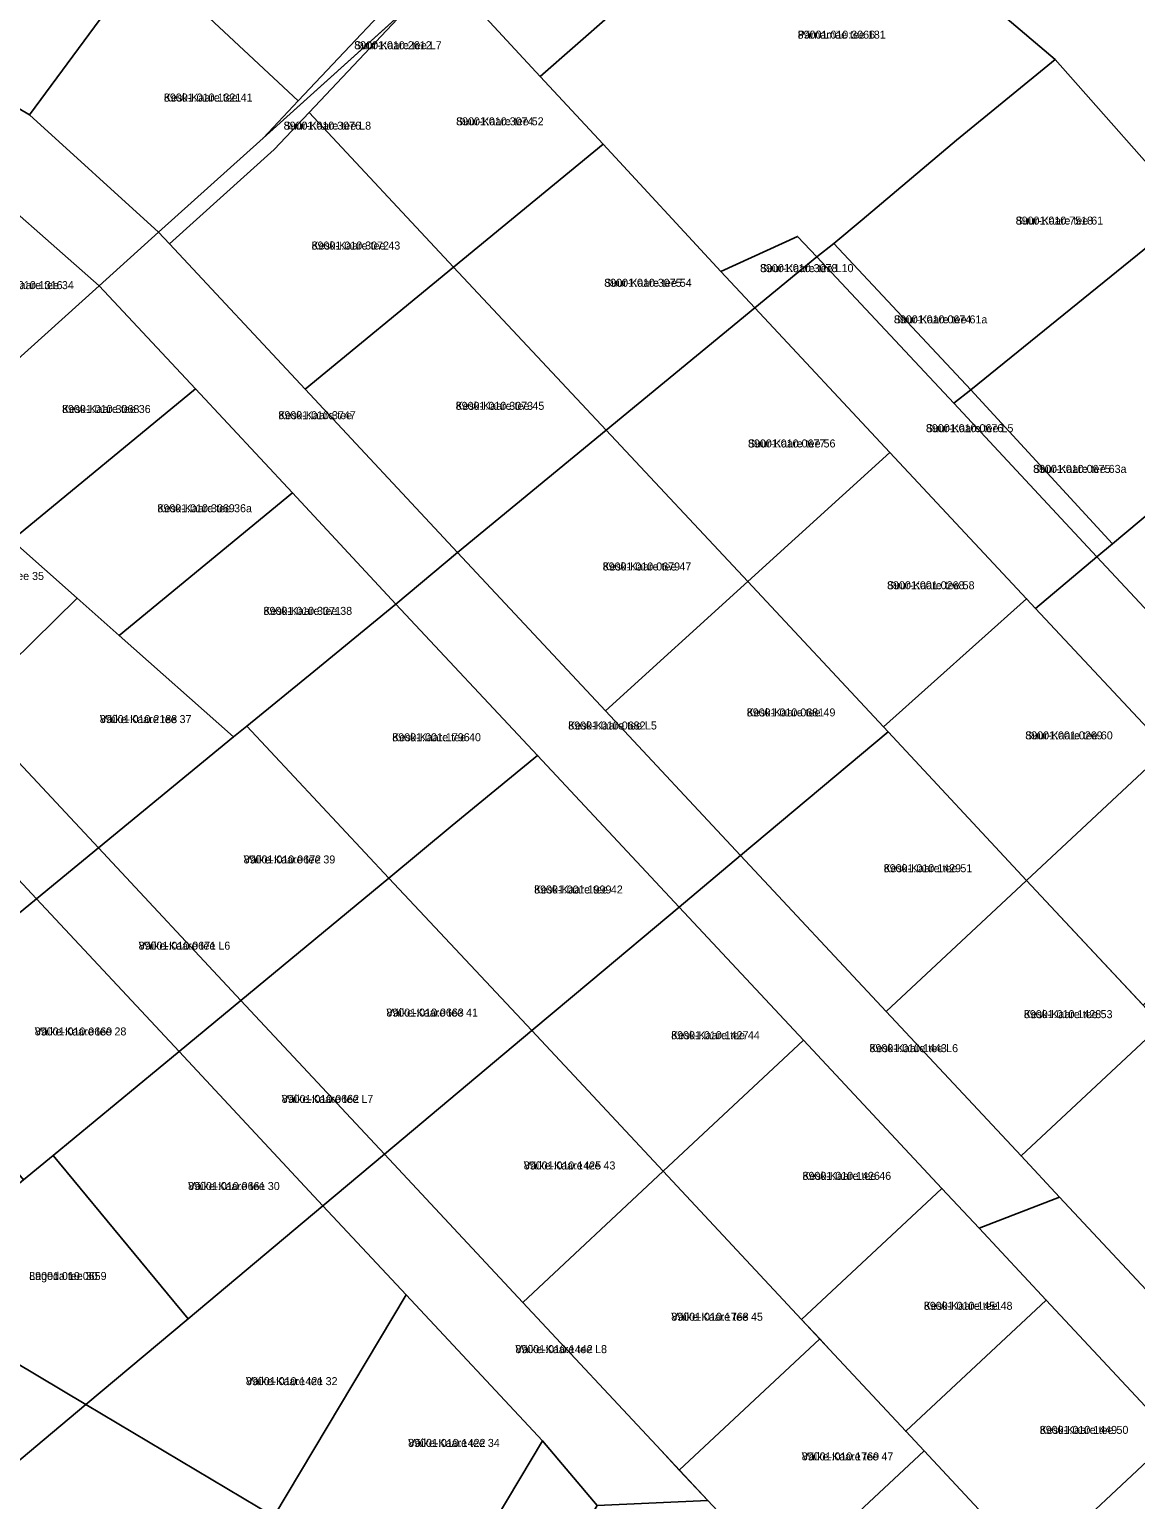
# Model space of a CAD drawing. Extents: x 526849 to 562296, y 6591741 to 6618546.
# Drawn here: x 548539.4 to 548746.7, y 6596665.2 to 6596940.7 of the extents above; entities that cross this region are included whole.
import ezdxf

# ---------------------------------------------------------------- set-up
doc = ezdxf.new("R2010")
doc.units = 0
for name, color, linetype in [('L_AADRESS', 7, 'Continuous'), ('PIIR', 7, 'Continuous'), ('TUNNUS', 7, 'Continuous')]:
    doc.layers.add(name, color=color, linetype=linetype)

msp = doc.modelspace()

# ---------------------------------------------------------------- linework, layer by layer
at = {"layer": 'PIIR'}
for points in [[(548635.14, 6596931.86), (548674.5, 6596966.36), (548653.8, 6596983.92), (548663.62, 6596992.77), (548731.64, 6596935.04), (548713.16, 6596919.89), (548695.51, 6596905.01), (548690.14, 6596900.55), (548687.01, 6596898.06), (548683.37, 6596901.89), (548669.02, 6596895.33), (548646.93, 6596919.15)], [(548624.14, 6596943.73), (548635.1, 6596953.6), (548629.61, 6596959.48), (548646.06, 6596976.95), (548653.8, 6596983.92), (548674.5, 6596966.36), (548635.14, 6596931.86)], [(548564.76, 6596950.65), (548586.85, 6596979.08), (548614.58, 6596953.6), (548589.77, 6596927.27)], [(548527.03, 6596973.58), (548538.19, 6596968), (548560.79, 6596953.66), (548539.44, 6596924.68), (548511.98, 6596940.88)], [(548299.97, 6596894.58), (548328.12, 6596911), (548358.36, 6596928.64), (548387.76, 6596943.88), (548418.39, 6596952.73), (548450.18, 6596955.2), (548481.81, 6596951.2), (548511.98, 6596940.88), (548539.44, 6596924.68), (548563.62, 6596902.65), (548552.48, 6596892.61), (548526.47, 6596915.49), (548491.86, 6596932.76), (548446.84, 6596940.25), (548405.11, 6596934.11), (548367.93, 6596916.86), (548336.83, 6596898.72), (548314.44, 6596885.66)], [(548560.79, 6596953.66), (548564.76, 6596950.65), (548589.77, 6596927.27), (548583.2, 6596920.29), (548563.62, 6596902.65), (548539.44, 6596924.68)], [(548614.58, 6596953.6), (548617.34, 6596951.06), (548583.2, 6596920.29), (548589.77, 6596927.27)], [(548591.83, 6596925.07), (548610.49, 6596944.89), (548617.34, 6596951.06), (548624.14, 6596943.73), (548635.14, 6596931.86), (548646.93, 6596919.15), (548618.91, 6596896.13)], [(548563.62, 6596902.65), (548583.2, 6596920.29), (548610.49, 6596944.89), (548591.83, 6596925.07), (548585.3, 6596918.14), (548565.67, 6596900.46)], [(548713.16, 6596919.89), (548731.64, 6596935.04), (548756.96, 6596906.42), (548715.84, 6596873.15), (548690.14, 6596900.55), (548695.51, 6596905.01)], [(548565.67, 6596900.46), (548585.3, 6596918.14), (548591.83, 6596925.07), (548618.91, 6596896.13), (548591.07, 6596873.26)], [(548618.91, 6596896.13), (548646.93, 6596919.15), (548669.02, 6596895.33), (548675.38, 6596888.47), (548647.51, 6596865.57)], [(548526.47, 6596915.49), (548552.48, 6596892.61), (548525.69, 6596868.52), (548506.15, 6596885.77)], [(548782.29, 6596877.71), (548742.41, 6596844.29), (548715.84, 6596873.15), (548756.96, 6596906.42)], [(548608.06, 6596832.97), (548588.71, 6596853.81), (548570.52, 6596873.29), (548552.48, 6596892.61), (548563.62, 6596902.65), (548565.67, 6596900.46), (548591.07, 6596873.26), (548619.65, 6596842.66)], [(548669.02, 6596895.33), (548683.37, 6596901.89), (548687.01, 6596898.06), (548675.38, 6596888.47)], [(548687.01, 6596898.06), (548690.14, 6596900.55), (548715.84, 6596873.15), (548712.64, 6596870.64)], [(548712.64, 6596870.64), (548739.47, 6596841.83), (548727.96, 6596832.18), (548726.28, 6596833.98), (548700.66, 6596861.41), (548675.38, 6596888.47), (548687.01, 6596898.06)], [(548591.07, 6596873.26), (548618.91, 6596896.13), (548647.51, 6596865.57), (548619.65, 6596842.66)], [(548517.7, 6596861.27), (548525.69, 6596868.52), (548552.48, 6596892.61), (548570.52, 6596873.29), (548536.09, 6596844.96)], [(548700.66, 6596861.41), (548674.02, 6596837.19), (548647.51, 6596865.57), (548675.38, 6596888.47)], [(548739.47, 6596841.83), (548742.41, 6596844.29), (548782.29, 6596877.71), (548799.28, 6596856.64), (548759.95, 6596819.9)], [(548536.09, 6596844.96), (548570.52, 6596873.29), (548588.71, 6596853.81), (548556.23, 6596827.09), (548548.37, 6596834.07)], [(548742.41, 6596844.29), (548739.47, 6596841.83), (548712.64, 6596870.64), (548715.84, 6596873.15)], [(548674.02, 6596837.19), (548647.37, 6596812.98), (548619.65, 6596842.66), (548647.51, 6596865.57)], [(548517.7, 6596861.27), (548548.37, 6596834.07), (548527.61, 6596813.74), (548499.49, 6596843.85)], [(548699.48, 6596809.98), (548674.02, 6596837.19), (548700.66, 6596861.41), (548726.28, 6596833.98)], [(548556.23, 6596827.09), (548588.71, 6596853.81), (548608.06, 6596832.97), (548592.71, 6596820.35), (548580.17, 6596810.13), (548577.64, 6596808.1)], [(548499.49, 6596843.85), (548527.61, 6596813.74), (548552.32, 6596787.29), (548540.71, 6596777.74), (548520.92, 6596798.93), (548493.28, 6596776.21), (548489.47, 6596780.84), (548516.82, 6596803.32), (548488.65, 6596833.48)], [(548647.37, 6596812.98), (548672.7, 6596785.86), (548661.19, 6596776.21), (548634.65, 6596804.63), (548608.06, 6596832.97), (548619.65, 6596842.66)], [(548727.96, 6596832.18), (548739.47, 6596841.83), (548759.95, 6596819.9), (548780.77, 6596797.61), (548802.27, 6596774.59), (548819.99, 6596755.61), (548804.91, 6596749.79), (548803.13, 6596751.69), (548777.88, 6596778.73), (548752.62, 6596805.77)], [(548700.33, 6596809.02), (548672.7, 6596785.86), (548647.37, 6596812.98), (548674.02, 6596837.19), (548699.48, 6596809.98)], [(548548.37, 6596834.07), (548556.23, 6596827.09), (548577.64, 6596808.1), (548552.32, 6596787.29), (548527.61, 6596813.74)], [(548592.71, 6596820.35), (548608.06, 6596832.97), (548634.65, 6596804.63), (548618.64, 6596791.51), (548606.79, 6596781.6), (548580.17, 6596810.13)], [(548700.33, 6596809.02), (548699.48, 6596809.98), (548726.28, 6596833.98), (548727.96, 6596832.18), (548752.62, 6596805.77), (548726.31, 6596781.2)], [(548606.79, 6596781.6), (548579.03, 6596758.7), (548552.32, 6596787.29), (548577.64, 6596808.1), (548580.17, 6596810.13)], [(548672.7, 6596785.86), (548700.33, 6596809.02), (548726.31, 6596781.2), (548700, 6596756.62)], [(548752.62, 6596805.77), (548774.47, 6596782.38), (548748.16, 6596757.81), (548726.31, 6596781.2)], [(548618.64, 6596791.51), (548634.65, 6596804.63), (548661.19, 6596776.21), (548644.6, 6596762.3), (548633.56, 6596753.05), (548606.79, 6596781.6)], [(548520.92, 6596798.93), (548540.71, 6596777.74), (548513.36, 6596755.26), (548505.55, 6596748.86), (548485.77, 6596770.04), (548493.28, 6596776.21)], [(548579.03, 6596758.7), (548567.44, 6596749.13), (548540.71, 6596777.74), (548552.32, 6596787.29)], [(548672.7, 6596785.86), (548700, 6596756.62), (548725.26, 6596729.58), (548732.49, 6596721.84), (548717.41, 6596716.02), (548710.43, 6596723.49), (548684.49, 6596751.26), (548661.19, 6596776.21)], [(548633.56, 6596753.05), (548605.93, 6596729.89), (548579.03, 6596758.7), (548606.79, 6596781.6)], [(548700, 6596756.62), (548726.31, 6596781.2), (548751.57, 6596754.16), (548725.26, 6596729.58)], [(548567.44, 6596749.13), (548543.86, 6596729.67), (548538.29, 6596725.07), (548513.36, 6596755.26), (548540.71, 6596777.74)], [(548633.56, 6596753.05), (548644.6, 6596762.3), (548661.19, 6596776.21), (548684.49, 6596751.26), (548658.18, 6596726.69)], [(548605.93, 6596729.89), (548594.42, 6596720.24), (548567.44, 6596749.13), (548579.03, 6596758.7)], [(548631.87, 6596702.12), (548605.93, 6596729.89), (548633.56, 6596753.05), (548658.18, 6596726.69)], [(548725.26, 6596729.58), (548751.57, 6596754.16), (548768.7, 6596735.81), (548776.82, 6596727.12), (548750.51, 6596702.54), (548732.49, 6596721.84)], [(548684.49, 6596751.26), (548710.43, 6596723.49), (548684.12, 6596698.92), (548658.18, 6596726.69)], [(548594.42, 6596720.24), (548569.14, 6596699.05), (548543.86, 6596729.67), (548567.44, 6596749.13)], [(548569.14, 6596699.05), (548549.98, 6596682.99), (548513.61, 6596704.69), (548538.29, 6596725.07), (548543.86, 6596729.67)], [(548609.99, 6596703.57), (548594.42, 6596720.24), (548605.93, 6596729.89), (548631.87, 6596702.12), (548657.81, 6596674.35), (548666.54, 6596665.01), (548645.83, 6596664.09), (548635.57, 6596676.18)], [(548631.87, 6596702.12), (548658.18, 6596726.69), (548684.12, 6596698.92), (548687.53, 6596695.27), (548661.21, 6596670.69), (548657.81, 6596674.35)], [(548710.43, 6596723.49), (548717.41, 6596716.02), (548729.97, 6596702.56), (548703.66, 6596677.99), (548689.37, 6596693.3), (548684.12, 6596698.92)], [(548549.98, 6596682.99), (548569.14, 6596699.05), (548594.42, 6596720.24), (548609.99, 6596703.57), (548585.19, 6596661.99)], [(548717.41, 6596716.02), (548732.49, 6596721.84), (548750.51, 6596702.54), (548775.77, 6596675.5), (548808.35, 6596640.61), (548791.96, 6596636.19), (548787.84, 6596640.61), (548753.86, 6596676.98), (548729.97, 6596702.56)], [(548549.98, 6596682.99), (548531.55, 6596667.55), (548494.93, 6596689.27), (548513.61, 6596704.69)], [(548585.19, 6596661.99), (548609.99, 6596703.57), (548635.57, 6596676.18), (548616.1, 6596643.54)], [(548729.97, 6596702.56), (548753.86, 6596676.98), (548727.55, 6596652.41), (548707.08, 6596674.33), (548703.66, 6596677.99)], [(548661.21, 6596670.69), (548687.53, 6596695.27), (548689.37, 6596693.3), (548703.66, 6596677.99), (548707.08, 6596674.33), (548680.77, 6596649.76), (548678.34, 6596652.36), (548666.54, 6596665.01)], [(548491.4, 6596633.9), (548501.45, 6596642.32), (548531.55, 6596667.55), (548549.98, 6596682.99), (548585.19, 6596661.99), (548616.1, 6596643.54), (548635.57, 6596676.18), (548645.83, 6596664.09), (548628.98, 6596635.86), (548637.6, 6596594.08), (548620.26, 6596589.09), (548614.25, 6596618.21), (548603.4, 6596624.68), (548564.29, 6596648.02), (548540.64, 6596662.12), (548508.18, 6596634.91), (548497.83, 6596626.24)], [(548753.86, 6596676.98), (548787.84, 6596640.61), (548782.42, 6596639.13), (548784, 6596634.05), (548752.6, 6596625.58), (548727.55, 6596652.41)], [(548687.37, 6596655.88), (548707.08, 6596674.33), (548727.55, 6596652.41), (548752.6, 6596625.58), (548723.11, 6596617.58)]]:
    msp.add_lwpolyline(points, close=True, dxfattribs=at)
msp.add_lwpolyline([(549073.92, 6596556.03), (548977.86, 6596659.6), (548967.58, 6596670.72), (548940.95, 6596697.87), (548918.31, 6596719.48), (548898.02, 6596738.85), (548884.29, 6596751.96), (548877.85, 6596759.69), (548866.33, 6596773.5), (548862.16, 6596778.67), (548838.31, 6596808.25), (548818.48, 6596832.84), (548799.28, 6596856.64), (548782.29, 6596877.71), (548756.96, 6596906.42), (548731.64, 6596935.04), (548663.62, 6596992.77)], dxfattribs=at)

# ---------------------------------------------------------------- texts
at = {"layer": 'L_AADRESS'}
for s, p in [('Pärnamäe tee 181', (548683.39, 6596938.93)), ('Suur-Kaare tee L7', (548600.28, 6596936.95)), ('Kesk-Kaare tee 41', (548564.61, 6596927.15)), ('Suur-Kaare tee 52', (548619.38, 6596922.69)), ('Suur-Kaare tee L8', (548587.05, 6596921.88)), ('Suur-Kaare tee 61', (548724.25, 6596904.09)), ('Kesk-Kaare tee 43', (548592.29, 6596899.42)), ('Suur-Kaare tee L10', (548676.34, 6596895.18)), ('Kesk-Kaare tee 34', (548531.11, 6596892)), ('Suur-Kaare tee 54', (548647.14, 6596892.44)), ('Suur-Kaare tee 61a', (548701.43, 6596885.58)), ('Kesk-Kaare tee 36', (548545.51, 6596868.79)), ('Kesk-Kaare tee', (548586.06, 6596867.63)), ('Kesk-Kaare tee 45', (548619.29, 6596869.38)), ('Suur-Kaare tee L5', (548707.43, 6596865.19)), ('Suur-Kaare tee 56', (548674.08, 6596862.33)), ('Suur-Kaare tee 63a', (548727.52, 6596857.56)), ('Kesk-Kaare tee 36a', (548563.38, 6596850.19)), ('Väike-Kaare tee 35', (548524.96, 6596837.5)), ('Kesk-Kaare tee 47', (548646.84, 6596839.28)), ('Suur-Kaare tee 58', (548700.15, 6596835.76)), ('Kesk-Kaare tee 38', (548583.27, 6596830.96)), ('Väike-Kaare tee 37', (548552.6, 6596810.68)), ('Kesk-Kaare tee L5', (548640.38, 6596809.48)), ('Kesk-Kaare tee 49', (548673.85, 6596811.93)), ('Kesk-Kaare tee 40', (548607.41, 6596807.28)), ('Suur-Kaare tee 60', (548726.05, 6596807.63)), ('Väike-Kaare tee 39', (548579.55, 6596784.38)), ('Kesk-Kaare tee 51', (548699.51, 6596782.74)), ('Kesk-Kaare tee 42', (548633.99, 6596778.75)), ('Väike-Kaare tee L6', (548559.87, 6596768.22)), ('Väike-Kaare tee 41', (548606.3, 6596755.69)), ('Kesk-Kaare tee 53', (548725.79, 6596755.39)), ('Väike-Kaare tee 28', (548540.4, 6596752.15)), ('Kesk-Kaare tee 44', (548659.68, 6596751.45)), ('Kesk-Kaare tee L6', (548696.84, 6596749.02)), ('Väike-Kaare tee L7', (548586.68, 6596739.51)), ('Väike-Kaare tee 43', (548632.05, 6596727.04)), ('Kesk-Kaare tee 46', (548684.3, 6596725.09)), ('Väike-Kaare tee 30', (548569.14, 6596723.18)), ('Lageda tee 30', (548539.36, 6596706.33)), ('Kesk-Kaare tee 48', (548707.04, 6596700.74)), ('Väike-Kaare tee 45', (548659.7, 6596698.69)), ('Väike-Kaare tee L8', (548630.48, 6596692.62)), ('Väike-Kaare tee 32', (548579.98, 6596686.62)), ('Kesk-Kaare tee 50', (548728.76, 6596677.49)), ('Väike-Kaare tee 34', (548610.38, 6596675.05)), ('Väike-Kaare tee 47', (548684.15, 6596672.52))]:
    msp.add_text(s, height=1.5, dxfattribs=at).set_placement(p)
at = {"layer": 'TUNNUS'}
for s, p in [('89001:010:3066', (548683.39, 6596938.93)), ('89001:010:2612', (548600.28, 6596936.95)), ('89001:010:1321', (548564.61, 6596927.15)), ('89001:010:3074', (548619.38, 6596922.69)), ('89001:010:3076', (548587.05, 6596921.88)), ('89001:010:7518', (548724.25, 6596904.09)), ('89001:010:3072', (548592.29, 6596899.42)), ('89001:010:3078', (548676.34, 6596895.18)), ('89001:010:1316', (548531.11, 6596892)), ('89001:010:3075', (548647.14, 6596892.44)), ('89001:010:0674', (548701.43, 6596885.58)), ('89001:010:3068', (548545.51, 6596868.79)), ('89001:010:3747', (548586.06, 6596867.63)), ('89001:010:3073', (548619.29, 6596869.38)), ('89001:010:0676', (548707.43, 6596865.19)), ('89001:010:0677', (548674.08, 6596862.33)), ('89001:010:0675', (548727.52, 6596857.56)), ('89001:010:3069', (548563.38, 6596850.19)), ('89001:010:0679', (548646.84, 6596839.28)), ('89001:001:0268', (548700.15, 6596835.76)), ('89001:010:3071', (548583.27, 6596830.96)), ('89001:010:2188', (548552.6, 6596810.68)), ('89001:010:0682', (548640.38, 6596809.48)), ('89001:010:0681', (548673.85, 6596811.93)), ('89001:001:1796', (548607.41, 6596807.28)), ('89001:001:0269', (548726.05, 6596807.63)), ('89001:010:0672', (548579.55, 6596784.38)), ('89001:010:1429', (548699.51, 6596782.74)), ('89001:001:1999', (548633.99, 6596778.75)), ('89001:010:0671', (548559.87, 6596768.22)), ('89001:010:0663', (548606.3, 6596755.69)), ('89001:010:1428', (548725.79, 6596755.39)), ('89001:010:0669', (548540.4, 6596752.15)), ('89001:010:1427', (548659.68, 6596751.45)), ('89001:010:1443', (548696.84, 6596749.02)), ('89001:010:0662', (548586.68, 6596739.51)), ('89001:010:1425', (548632.05, 6596727.04)), ('89001:010:1426', (548684.3, 6596725.09)), ('89001:010:0661', (548569.14, 6596723.18)), ('89001:010:0659', (548539.36, 6596706.33)), ('89001:010:1451', (548707.04, 6596700.74)), ('89001:010:1768', (548659.7, 6596698.69)), ('89001:010:1442', (548630.48, 6596692.62)), ('89001:010:1421', (548579.98, 6596686.62)), ('89001:010:1449', (548728.76, 6596677.49)), ('89001:010:1422', (548610.38, 6596675.05)), ('89001:010:1769', (548684.15, 6596672.52))]:
    msp.add_text(s, height=1.5, dxfattribs=at).set_placement(p)

doc.saveas('drawing.dxf')
